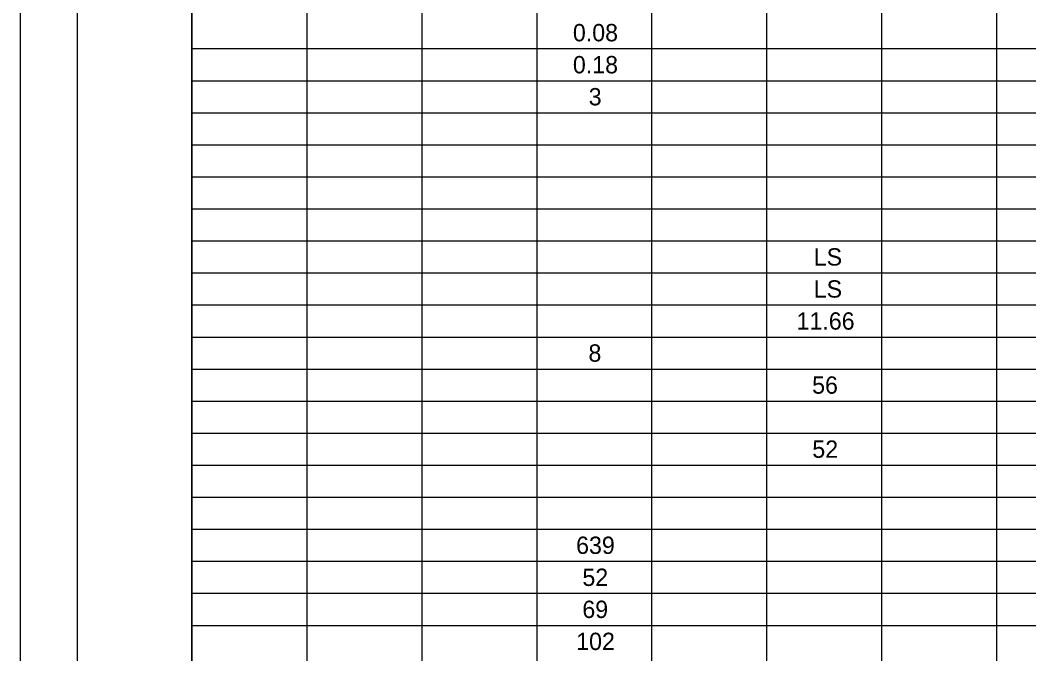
# Model space of a CAD drawing. Extents: x 0 to 34, y 0 to 22.
# Drawn here: x 0 to 8.82, y 10.89 to 16.43 of the extents above; entities that cross this region are included whole.
import ezdxf

# ---------------------------------------------------------------- set-up
doc = ezdxf.new("R2010")
doc.units = 0
for name, color, linetype in [('SH_Border', 7, 'Continuous'), ('SH_Cut_Line', 7, 'Continuous'), ('SH_Text', 7, 'Continuous')]:
    doc.layers.add(name, color=color, linetype=linetype)

msp = doc.modelspace()

# ---------------------------------------------------------------- linework, layer by layer
at = {"layer": 'SH_Border'}
for points in [[(0.5, 21.5), (1.5, 21.5), (1.5, 0.5), (0.5, 0.5)], [(1.5, 21.5), (33.5, 21.5), (33.5, 0.5), (1.5, 0.5)]]:
    msp.add_lwpolyline(points, close=True, dxfattribs=at)
at = {"layer": 'SH_Cut_Line'}
msp.add_lwpolyline([(0, 0), (34, 0), (34, 22), (0, 22)], close=True, dxfattribs=at)
at = {"layer": 'SH_Text'}
for p, q in [((1.5, 21.5), (1.5, 0.5)), ((2.5047, 20.94), (2.5047, 0.5)), ((3.5094, 20.94), (3.5094, 0.5)), ((4.5141, 20.94), (4.5141, 0.5)), ((5.5188, 20.94), (5.5188, 0.5)), ((6.5235, 20.94), (6.5235, 0.5)), ((7.5282, 20.94), (7.5282, 0.5)), ((8.5329, 20.94), (8.5329, 0.5)), ((1.5, 16.18), (32.0035, 16.18)), ((1.5, 15.9), (32.0035, 15.9)), ((1.5, 15.62), (32.0035, 15.62)), ((1.5, 15.34), (32.0035, 15.34)), ((1.5, 15.06), (32.0035, 15.06)), ((1.5, 14.78), (32.0035, 14.78)), ((1.5, 14.5), (32.0035, 14.5)), ((1.5, 14.22), (32.0035, 14.22)), ((1.5, 13.94), (32.0035, 13.94)), ((1.5, 13.66), (32.0035, 13.66)), ((1.5, 13.38), (32.0035, 13.38)), ((1.5, 13.1), (32.0035, 13.1)), ((1.5, 12.82), (32.0035, 12.82)), ((1.5, 12.54), (32.0035, 12.54)), ((1.5, 12.26), (32.0035, 12.26)), ((1.5, 11.98), (32.0035, 11.98)), ((1.5, 11.7), (32.0035, 11.7)), ((1.5, 11.42), (32.0035, 11.42)), ((1.5, 11.14), (32.0035, 11.14))]:
    msp.add_line(p, q, dxfattribs=at)

# ---------------------------------------------------------------- texts
for s, height, p in [('0.08', 0.15153, (4.8305, 16.2442)), ('0.18', 0.15153, (4.8305, 15.9642)), ('3', 0.1515, (4.9686, 15.6842)), ('LS', 0.15153, (6.9353, 14.2842)), ('LS', 0.15153, (6.9353, 14.0042)), ('11.66', 0.15153, (6.7853, 13.7242)), ('8', 0.1515, (4.9665, 13.4442)), ('56', 0.15153, (6.9213, 13.1642)), ('52', 0.15153, (6.923, 12.6042)), ('639', 0.15153, (4.8586, 11.7642)), ('52', 0.15153, (4.9136, 11.4842)), ('69', 0.15153, (4.9131, 11.2042)), ('102', 0.15153, (4.8592, 10.9242))]:
    msp.add_text(s, height=height, dxfattribs=at).set_placement(p)

doc.saveas('drawing.dxf')
